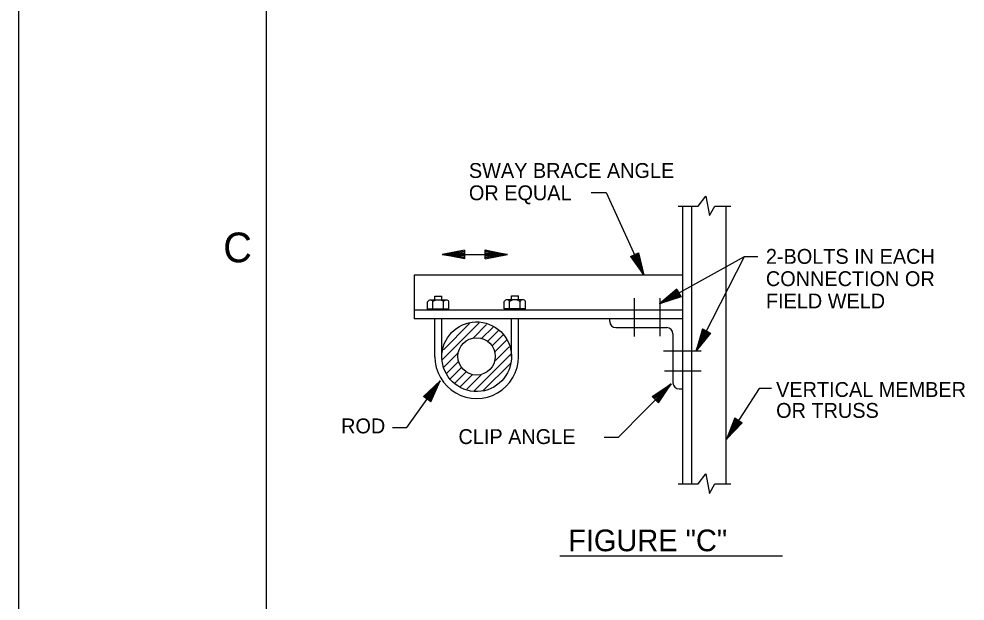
# Model space of a CAD drawing. Extents: x 9999.96 to 10005.26, y 9999.88 to 10002.38.
# Drawn here: x 9999.96 to 10000.597, y 10001.21 to 10001.601 of the extents above; entities that cross this region are included whole.
import ezdxf

# ---------------------------------------------------------------- set-up
doc = ezdxf.new("R2010")
doc.units = 0
doc.layers.add('Level 1', color=7, linetype='Continuous')
doc.layers.add('Level 2', color=7, linetype='Continuous')

msp = doc.modelspace()

# ---------------------------------------------------------------- linework, layer by layer
at = {"layer": 'Level 1'}
for p, q in [((9999.96033, 9999.88453), (9999.96033, 10002.38453)), ((10000.127, 9999.9262), (10000.127, 10002.34286))]:
    msp.add_line(p, q, dxfattribs=at)
at = {"layer": 'Level 2'}
for p, q in [((10000.40696, 10001.47539), (10000.40696, 10001.28855)), ((10000.41317, 10001.28849), (10000.41317, 10001.47539)), ((10000.43643, 10001.28849), (10000.43643, 10001.47539)), ((10000.26028, 10001.44579), (10000.24523, 10001.44279)), ((10000.24523, 10001.44279), (10000.26028, 10001.44503)), ((10000.24523, 10001.44279), (10000.2603, 10001.44419)), ((10000.24523, 10001.44279), (10000.26028, 10001.44351)), ((10000.26029, 10001.44281), (10000.24523, 10001.44279)), ((10000.24523, 10001.44279), (10000.28922, 10001.44279)), ((10000.26027, 10001.43977), (10000.24523, 10001.44279)), ((10000.24523, 10001.44279), (10000.26029, 10001.44131)), ((10000.24523, 10001.44279), (10000.26028, 10001.44058)), ((10000.24523, 10001.44279), (10000.26028, 10001.44205)), ((10000.26028, 10001.44579), (10000.26027, 10001.43977)), ((10000.28922, 10001.44279), (10000.27415, 10001.4414)), ((10000.28922, 10001.44279), (10000.27416, 10001.44427)), ((10000.27416, 10001.44277), (10000.28922, 10001.44279)), ((10000.27417, 10001.43979), (10000.27418, 10001.44581)), ((10000.28922, 10001.44279), (10000.27417, 10001.445)), ((10000.28922, 10001.44279), (10000.27417, 10001.44353)), ((10000.27417, 10001.43979), (10000.28922, 10001.44279)), ((10000.28922, 10001.44279), (10000.27417, 10001.44207)), ((10000.28922, 10001.44279), (10000.27417, 10001.44055)), ((10000.27418, 10001.44581), (10000.28922, 10001.44279)), ((10000.37192, 10001.44135), (10000.37741, 10001.44384)), ((10000.37192, 10001.44135), (10000.38088, 10001.4289)), ((10000.38088, 10001.4289), (10000.37261, 10001.44168)), ((10000.38088, 10001.4289), (10000.37336, 10001.44204)), ((10000.38088, 10001.4289), (10000.37399, 10001.4423)), ((10000.37463, 10001.4426), (10000.38088, 10001.4289)), ((10000.38088, 10001.4289), (10000.37531, 10001.44291)), ((10000.38088, 10001.4289), (10000.37599, 10001.44322)), ((10000.38088, 10001.4289), (10000.37665, 10001.44351)), ((10000.37741, 10001.44384), (10000.38088, 10001.4289)), ((10000.40696, 10001.42885), (10000.22627, 10001.42885)), ((10000.22627, 10001.42885), (10000.22627, 10001.39939)), ((10000.40314, 10001.41954), (10000.39144, 10001.40959)), ((10000.39144, 10001.40959), (10000.40351, 10001.41886)), ((10000.39144, 10001.40959), (10000.40394, 10001.41815)), ((10000.39144, 10001.40959), (10000.40424, 10001.41754)), ((10000.40459, 10001.41694), (10000.39144, 10001.40959)), ((10000.39144, 10001.40959), (10000.40495, 10001.41627)), ((10000.39144, 10001.40959), (10000.40532, 10001.41563)), ((10000.40314, 10001.41954), (10000.40605, 10001.41427)), ((10000.23542, 10001.40607), (10000.23542, 10001.41102)), ((10000.24793, 10001.41214), (10000.23721, 10001.41215)), ((10000.23898, 10001.40607), (10000.23898, 10001.41106)), ((10000.24028, 10001.41471), (10000.24497, 10001.41471)), ((10000.24028, 10001.41208), (10000.24028, 10001.41471)), ((10000.24497, 10001.41214), (10000.24497, 10001.41471)), ((10000.24618, 10001.40607), (10000.24618, 10001.41106)), ((10000.24973, 10001.40607), (10000.24973, 10001.41106)), ((10000.28698, 10001.40624), (10000.28698, 10001.41119)), ((10000.29949, 10001.4123), (10000.28877, 10001.41231)), ((10000.29054, 10001.40624), (10000.29054, 10001.41123)), ((10000.29184, 10001.41488), (10000.29653, 10001.41488)), ((10000.29184, 10001.41225), (10000.29184, 10001.41488)), ((10000.29653, 10001.4123), (10000.29653, 10001.41488)), ((10000.29774, 10001.40624), (10000.29774, 10001.41123)), ((10000.30129, 10001.40624), (10000.30129, 10001.41123)), ((10000.37471, 10001.38771), (10000.37471, 10001.41336)), ((10000.39144, 10001.40959), (10000.40567, 10001.41499)), ((10000.40605, 10001.41427), (10000.39144, 10001.40959)), ((10000.39176, 10001.41336), (10000.39176, 10001.38789)), ((10000.22627, 10001.40559), (10000.40696, 10001.40559)), ((10000.24973, 10001.40607), (10000.23542, 10001.40607)), ((10000.30129, 10001.40624), (10000.28698, 10001.40624)), ((10000.40696, 10001.39939), (10000.22627, 10001.39939)), ((10000.24028, 10001.374), (10000.24028, 10001.39928)), ((10000.24497, 10001.374), (10000.24497, 10001.39928)), ((10000.24548, 10001.37211), (10000.27019, 10001.39682)), ((10000.29184, 10001.374), (10000.29184, 10001.39945)), ((10000.29653, 10001.374), (10000.29653, 10001.39945)), ((10000.35801, 10001.39774), (10000.35801, 10001.39938)), ((10000.246, 10001.37867), (10000.26365, 10001.39631)), ((10000.26621, 10001.3868), (10000.27513, 10001.39573)), ((10000.27175, 10001.38631), (10000.27944, 10001.394)), ((10000.27564, 10001.38417), (10000.28346, 10001.39199)), ((10000.36218, 10001.39357), (10000.39638, 10001.39357)), ((10000.42039, 10001.39267), (10000.41625, 10001.37789)), ((10000.41625, 10001.37789), (10000.42106, 10001.39232)), ((10000.41625, 10001.37789), (10000.42182, 10001.39196)), ((10000.41625, 10001.37789), (10000.42242, 10001.39164)), ((10000.42304, 10001.39133), (10000.41625, 10001.37789)), ((10000.41625, 10001.37789), (10000.42372, 10001.39098)), ((10000.41625, 10001.37789), (10000.42439, 10001.39066)), ((10000.41625, 10001.37789), (10000.42502, 10001.39031)), ((10000.42039, 10001.39267), (10000.42575, 10001.38994)), ((10000.27866, 10001.38116), (10000.28621, 10001.3887)), ((10000.28095, 10001.37742), (10000.28859, 10001.38505)), ((10000.40054, 10001.38941), (10000.40054, 10001.35648)), ((10000.42575, 10001.38994), (10000.41625, 10001.37789)), ((10000.28108, 10001.37152), (10000.29032, 10001.38075)), ((10000.39427, 10001.37802), (10000.41956, 10001.37802)), ((10000.24604, 10001.36665), (10000.25598, 10001.37658)), ((10000.26673, 10001.35113), (10000.29155, 10001.37595)), ((10000.24805, 10001.36261), (10000.25601, 10001.37057)), ((10000.25063, 10001.35916), (10000.25842, 10001.36695)), ((10000.27286, 10001.35122), (10000.29109, 10001.36946)), ((10000.25372, 10001.35622), (10000.26134, 10001.36384)), ((10000.25747, 10001.35393), (10000.26541, 10001.36186)), ((10000.26173, 10001.35217), (10000.27142, 10001.36185)), ((10000.41956, 10001.36439), (10000.3948, 10001.36439)), ((10000.2327, 10001.34724), (10000.24395, 10001.35768)), ((10000.24395, 10001.35768), (10000.23336, 10001.34675)), ((10000.24395, 10001.35768), (10000.23394, 10001.34631)), ((10000.24395, 10001.35768), (10000.23455, 10001.34589)), ((10000.23516, 10001.34544), (10000.24395, 10001.35768)), ((10000.24395, 10001.35768), (10000.23574, 10001.34504)), ((10000.24395, 10001.35768), (10000.23627, 10001.34463)), ((10000.24395, 10001.35768), (10000.23696, 10001.34416)), ((10000.23758, 10001.34371), (10000.24395, 10001.35768)), ((10000.38653, 10001.34725), (10000.39925, 10001.35583)), ((10000.39925, 10001.35583), (10000.3871, 10001.34667)), ((10000.39925, 10001.35583), (10000.38761, 10001.34616)), ((10000.39925, 10001.35583), (10000.38815, 10001.34564)), ((10000.38868, 10001.34509), (10000.39925, 10001.35583)), ((10000.39925, 10001.35583), (10000.38919, 10001.34461)), ((10000.39925, 10001.35583), (10000.38965, 10001.34413)), ((10000.39925, 10001.35583), (10000.39026, 10001.34355)), ((10000.39081, 10001.34301), (10000.39925, 10001.35583)), ((10000.40471, 10001.35231), (10000.40701, 10001.35231)), ((10000.23758, 10001.34371), (10000.2327, 10001.34724)), ((10000.39081, 10001.34301), (10000.38653, 10001.34725)), ((10000.44216, 10001.33288), (10000.43648, 10001.31861)), ((10000.44216, 10001.33288), (10000.4472, 10001.32959)), ((10000.43645, 10001.32914), (10000.43645, 10001.32914)), ((10000.43648, 10001.31861), (10000.44279, 10001.33246)), ((10000.43648, 10001.31861), (10000.44351, 10001.33202)), ((10000.43648, 10001.31861), (10000.44406, 10001.33164)), ((10000.44466, 10001.33127), (10000.43648, 10001.31861)), ((10000.43648, 10001.31861), (10000.44529, 10001.33084)), ((10000.43648, 10001.31861), (10000.44592, 10001.33045)), ((10000.43648, 10001.31861), (10000.44652, 10001.33004)), ((10000.4472, 10001.32959), (10000.43648, 10001.31861)), ((10000.32442, 10001.24011), (10000.47434, 10001.24011))]:
    msp.add_line(p, q, dxfattribs=at)
for points in [[(10000.34549, 10001.48449), (10000.3556, 10001.48449), (10000.38088, 10001.4289)], [(10000.40403, 10001.47531), (10000.41751, 10001.47531), (10000.42269, 10001.48208), (10000.4252, 10001.46892), (10000.42871, 10001.47539), (10000.43952, 10001.47539)], [(10000.4576, 10001.4413), (10000.44842, 10001.4413), (10000.39144, 10001.40959)], [(10000.44842, 10001.4413), (10000.41625, 10001.37789)], [(10000.21178, 10001.32643), (10000.22144, 10001.32643), (10000.24395, 10001.35768)], [(10000.35423, 10001.32), (10000.36388, 10001.32), (10000.39925, 10001.35583)], [(10000.4668, 10001.35261), (10000.45853, 10001.35261), (10000.43648, 10001.31861)], [(10000.40403, 10001.28848), (10000.41751, 10001.28848), (10000.42269, 10001.29525), (10000.4252, 10001.28208), (10000.42871, 10001.28855), (10000.43952, 10001.28855)]]:
    msp.add_lwpolyline(points, dxfattribs=at)
msp.add_circle((10000.26836, 10001.37423), 0.01258, dxfattribs=at)
for centre, radius, start, end in [((10000.23721, 10001.41013), 0.002, 28.1609, 153.21731), ((10000.24258, 10001.40553), 0.00662, 57.05703, 122.99384), ((10000.24795, 10001.41014), 0.002, 27.96581, 152.1123), ((10000.28877, 10001.41029), 0.002, 28.1609, 153.21731), ((10000.29414, 10001.40569), 0.00662, 57.05703, 122.99384), ((10000.29951, 10001.41031), 0.002, 27.96581, 152.1123), ((10000.36218, 10001.39774), 0.00417, 180, 270), ((10000.39638, 10001.38941), 0.00417, 0, 90), ((10000.26841, 10001.374), 0.02813, 179.9664, 0), ((10000.40471, 10001.35648), 0.00417, 180, 270)]:
    msp.add_arc(centre, radius, start, end, dxfattribs=at)
msp.add_ellipse((10000.26841, 10001.374), major_axis=(0.00406, 0.02308), ratio=0.999997, dxfattribs=at)

# ---------------------------------------------------------------- texts
at = {"layer": 'Level 1'}
msp.add_text('C', height=0.02, dxfattribs=at).set_placement((10000.09783, 10001.43754))
at = {"layer": 'Level 2'}
for s, height, p in [('SWAY BRACE ANGLE', 0.01, (10000.2632, 10001.49428)), ('OR EQUAL', 0.01, (10000.2632, 10001.47928)), ('2-BOLTS IN EACH', 0.01, (10000.46307, 10001.43651)), ('CONNECTION OR', 0.01, (10000.46307, 10001.42151)), ('FIELD WELD', 0.01, (10000.46307, 10001.40651)), ('VERTICAL MEMBER', 0.01, (10000.46996, 10001.34695)), ('OR TRUSS', 0.01, (10000.46997, 10001.33288)), ('ROD', 0.01, (10000.17718, 10001.32247)), ('CLIP ANGLE', 0.01, (10000.25616, 10001.31527)), ('FIGURE "C"', 0.014583, (10000.32999, 10001.24315))]:
    msp.add_text(s, height=height, dxfattribs=at).set_placement(p)

doc.saveas('drawing.dxf')
